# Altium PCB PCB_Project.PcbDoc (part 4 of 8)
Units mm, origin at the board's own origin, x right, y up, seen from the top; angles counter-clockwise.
Board outline 250 x 200 mm, 6 copper layers (Top Shielding/Sig, Sig 1, PWR, GND, Sig 4, Bottom Shielding/Sig), stack 1.568 mm thick; 736 components, 420 nets, 1929 pads, 2185 vias.
Unrouted connection lines stored in the file: 47.
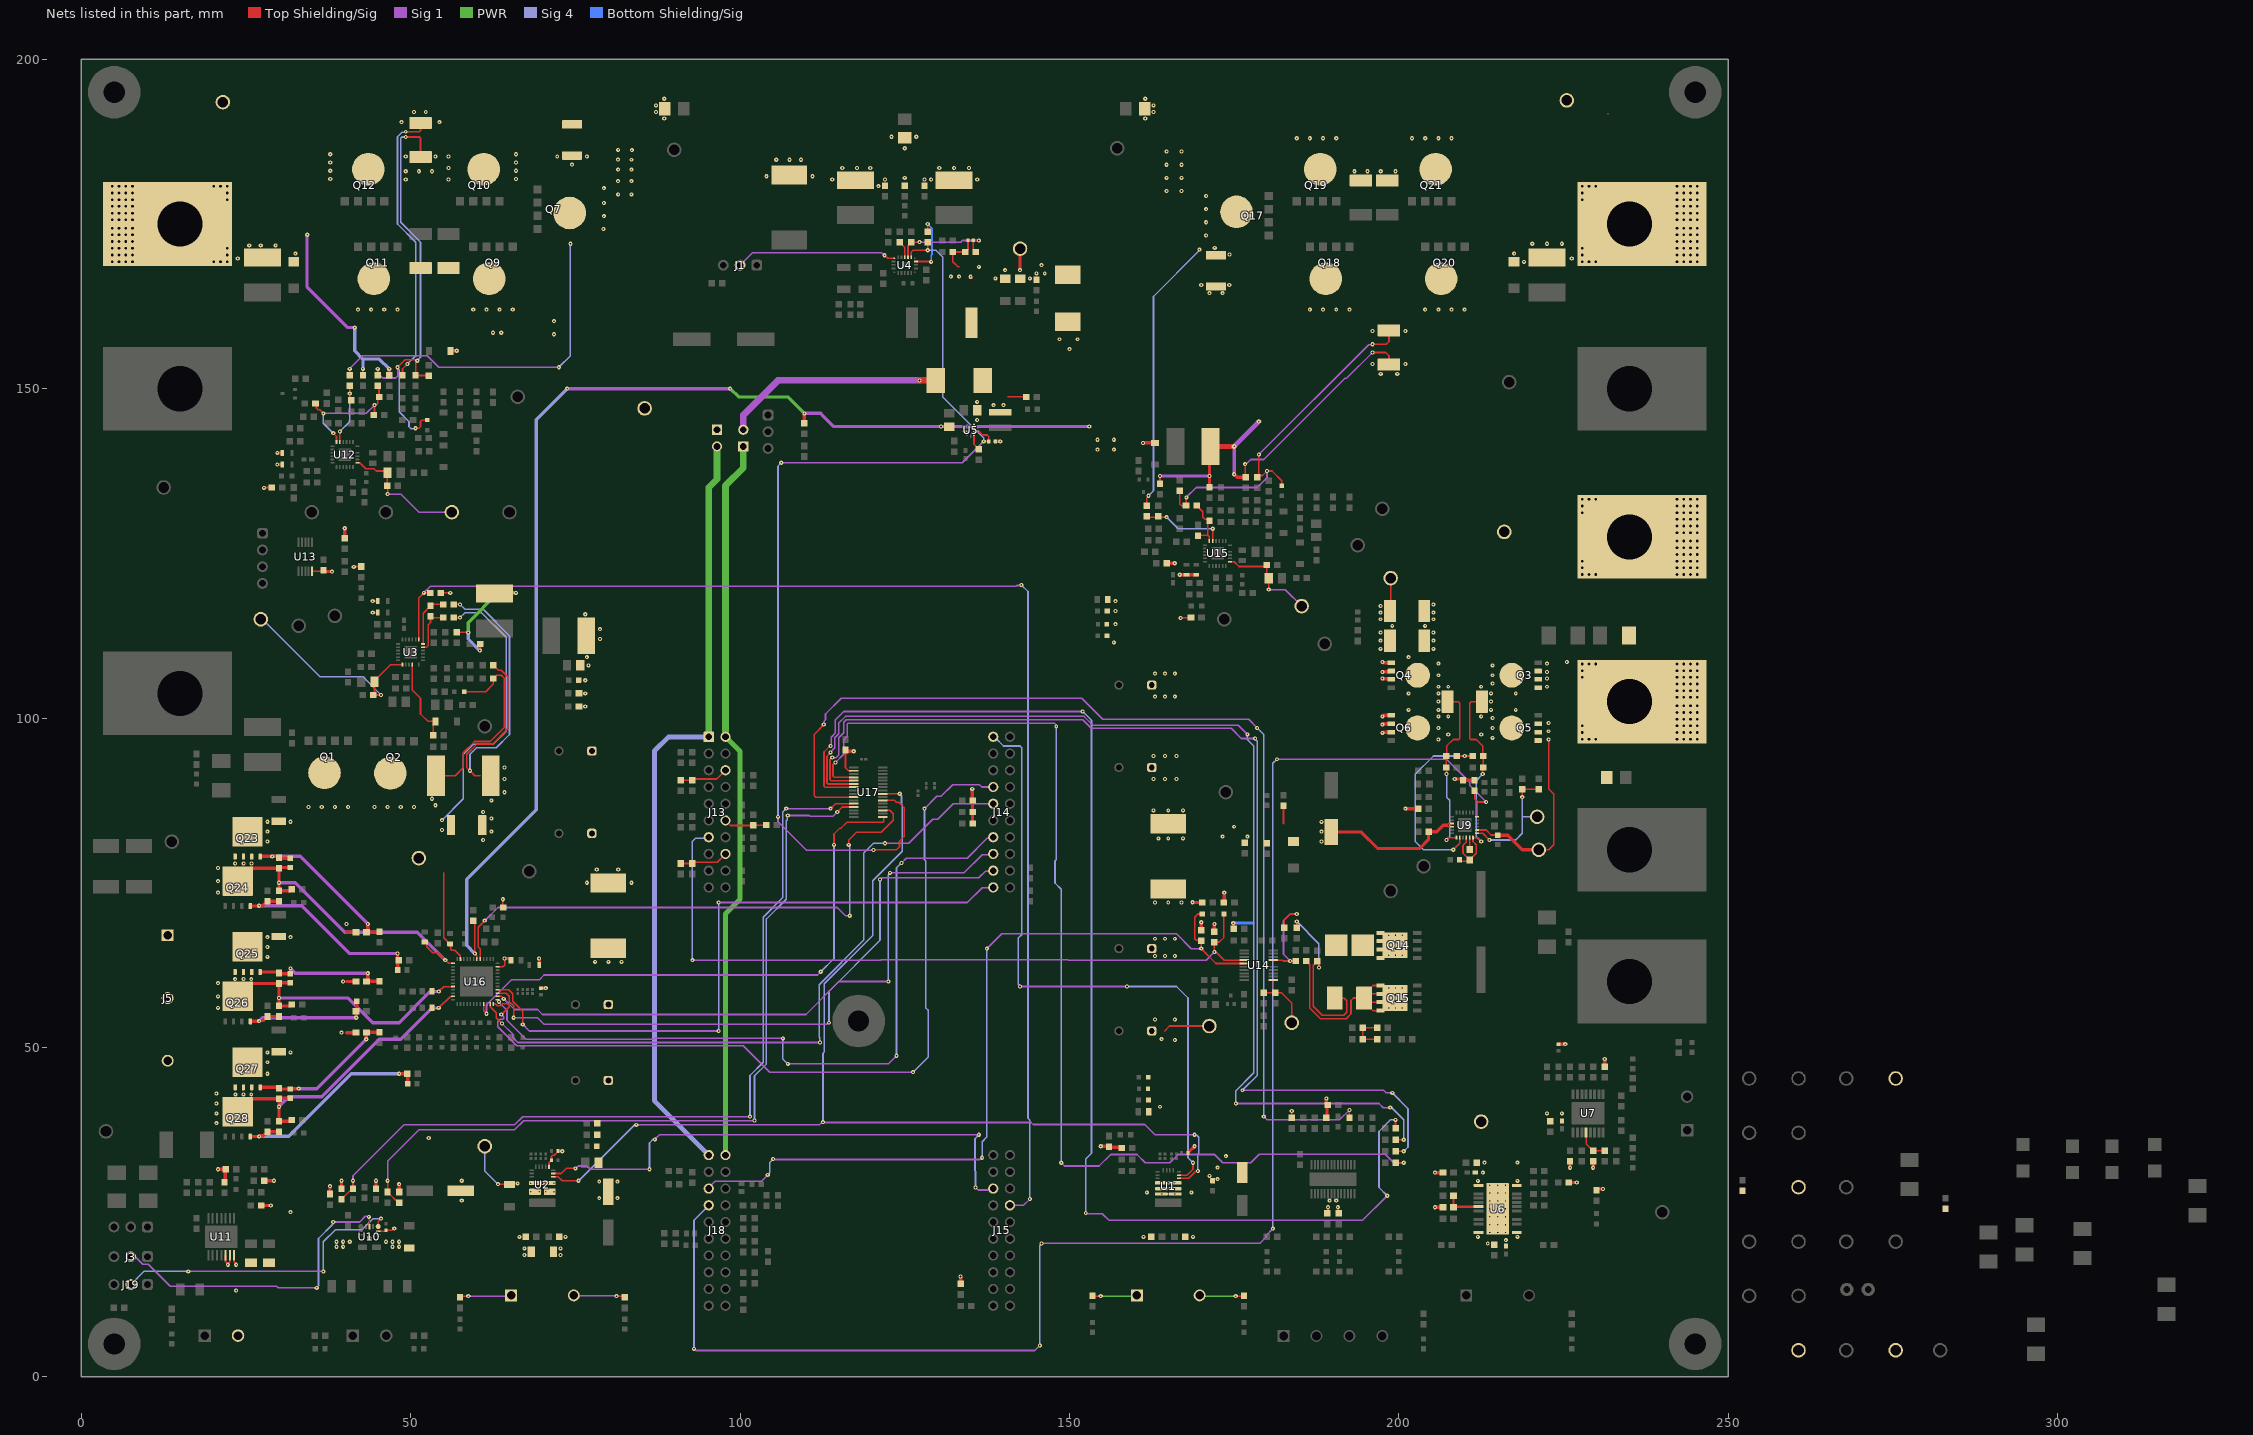
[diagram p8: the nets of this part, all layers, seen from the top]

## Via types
v1: diameter 0.635, hole 0.254, Top Shielding/Sig to Bottom Shielding/Sig, tented both sides, 778 vias
v2: diameter 0.6, hole 0.254, Top Shielding/Sig to Bottom Shielding/Sig, tented both sides, 726 vias
v3: diameter 0.813, hole 0.406, Top Shielding/Sig to Bottom Shielding/Sig, 522 vias
v4: diameter 0.5, hole 0.2, Top Shielding/Sig to Bottom Shielding/Sig, tented both sides, 95 vias
v5: diameter 0.5, hole 0.2, Top Shielding/Sig to Bottom Shielding/Sig, 39 vias
v6: diameter 0.635, hole 0.254, Top Shielding/Sig to Bottom Shielding/Sig, 10 vias
v7: diameter 0.63, hole 0.33, Top Shielding/Sig to Bottom Shielding/Sig, tented both sides, 6 vias
v8: diameter 0.75, hole 0.254, Top Shielding/Sig to Bottom Shielding/Sig, tented both sides, 6 vias
v9: diameter 0.5, hole 0.2, Top Shielding/Sig to Bottom Shielding/Sig, tented top, 3 vias

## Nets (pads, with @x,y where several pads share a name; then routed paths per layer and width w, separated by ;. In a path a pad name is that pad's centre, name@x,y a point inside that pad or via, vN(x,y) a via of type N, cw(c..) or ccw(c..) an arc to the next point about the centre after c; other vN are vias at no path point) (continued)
3V3: C23.1 C105.1 C128.1 C189.2 C199.1 D53.2 D54.2 J16.1 R3.2 R4.2 R6.1 R18.1 R35.2 R39.2 R40.2 R41.2 R61.2 R63.1 R64.2 R66.2 R71.2 R76.1 R79.2 R82.2 R88.1 R97.2 R98.2 R104.2 R123.2 R124.2 R125.2 R129.2 R130.2 R134.2 R136.2 R138.2 R142.2 R146.2 R149.2 R156.2 R183.2 R184.2 R186.2 R208.1 R210.1 R214.2 R215.2 R244.2 R245.2 R247.2 R257.1 R262.2 R267.2 R290.1 R291.1 R292.1 R297.2 R302.2 TP41.1 U2.11 U10.5 U13.10 U16.23 U17.2 | length 81.7
  Top Shielding/Sig w0.2: U16.23@63.212,62.25 64,62.25 64.25,62.5 v1(64.25,63.5) ; C189.2@64.995,63.5 C189.2@65.245,63.25
  Top Shielding/Sig w0.25: v2@27.75,135 R183.2@28.9,135 ; U13.10@35,122.5 35,122.325 35.025,122.3 C128.1@36.6,122.3 ; v1@41.5,123 R39.2@42.5,123 ; v1(44.25,116) R40.2@45,116 ; v1(44.25,117.75) R41.2@45,117.75 ; U10.5@45.1,22.075 46.075,22.075 C105.1@46.25,22.25 47.161,22.25 47.411,22.5 v1(47.5,22.5) ; R35.2@54.55,119 v1(56,119) ; v1(64,72.5) 64,71.3 R267.2@64.05,71.25 ; U2.11@71,31.875 71,32.5 C23.1@71.25,32.75 ; C23.1@71.375,32.875 71.375,33.479 71.521,33.625 71.8,33.625 72.375,34.2 R18.1@72.375,34.25 v1(73,34.25) ; C199.1@116,95.15 116,92.444 116.419,92.025 116.975,92.025 U17.2@117,92 ; v2@167,115.25 R244.2@168.45,115.25 ; R215.2@173.45,72 R215.2@173.5,72.05 ; R98.2@183.75,39.3 v1(183.75,40.344)
  Top Shielding/Sig w0.5: v1(20.75,31.5) R136.2@21.95,31.5 21.85,31.4 21.85,29.65 R146.2@21.75,29.55 ; R142.2@27.3,26 v1(28.75,26) ; R149.2@27.8,29.75 v1(29.25,29.75) ; v2(29.75,138.5) R184.2@30.5,138.5 ; v2(29.75,140.25) R186.2@30.5,140.25 ; C128.1@36.95,122.25 v1@38.026,122.25 ; R134.2@37.75,27.75 v1(37.75,28.95) ; R129.2@39.5,28.55 v1(39.5,29.75) ; R302.2@40,127.3 v1(40,128.8) ; R138.2@44.75,28.55 v1(44.75,29.75) ; R130.2@48.25,28.05 v1(48.25,29.25) ; D53.2@56.025,155.75 v6(57,155.75) ; v1(64.25,63.5) C189.2@64.995,63.5 ; R262.2@69.5,62.5 v1(69.5,63.5) ; R257.1@69.75,59 v1(70.5,59) ; C199.1@116,95.15 116.2,94.95 v1(117.25,94.95) ; R156.2@133.5,14.1 v1@133.5,15.1 ; v1(135.25,89.25) 135.25,87.55 R290.1@135.3,87.5 R292.1@135.3,85.75 R291.1@135.3,84 ; R61.2@138.75,142 v1(139.5,142) ; v1(154.75,35) 155.95,35 R3.2@156,34.95 156.1,34.85 157.85,34.85 R4.2@157.95,34.75 ; v2@161.275,141.775 D54.2@163,141.775 ; R297.2@164.8,123.5 v1@165.75,123.5 ; v1(166.75,121.75) 167.55,121.75 R247.2@167.75,121.75 ; R247.2@167.921,121.75 168.096,121.75 169.05,121.75 R245.2@169.421,121.75 ; R6.1@168,34 168,34.05 168.05,34.05 v1(169,35) ; v1@169,72 R214.2@170.15,72 ; R208.1@170,67.8 v1(170,69) ; R210.1@172,67.55 v1(172,68.75) ; R215.2@173.5,72.05 v1@173.5,73.25 ; R97.2@189,39.3 189.1,39.4 189.1,41.15 R104.2@189.2,41.25 189,41.45 v1(189,42.25) ; v1(201,86.25) R125.2@202.95,86.25 ; v1(205.5,25.75) R71.2@206.7,25.75 ; v1(205.5,31) R63.1@206.7,31 ; v1(208.5,90.75) 209.55,90.75 R124.2@209.75,90.55 R123.2@211.5,90.55 ; R88.1@224.25,50.5 v1(225.25,50.5) ; R66.2@225.8,29.5 v1(227,29.5) ; v1(226,31.75) R76.1@226,32.7 ; v1(229.5,31.75) R79.2@229.5,32.7 ; R64.2@230,28.3 230.2,28.5 v1(231,28.5) ; R82.2@231.25,47.05 v1(231.25,48.25)
  other v1: 133.459,15.219 168.701,72.028 173.5,73.5 38.056,122.231 41.348,122.954 166,123.5
  other v2: 166.893,115.196 27.727,134.945 161.154,141.744
3V3_MCU_12: J13.1 J16.2 J18.41 | length 118.3
  PWR w1: J13.1@95.25,97.155 95.25,135 96.5,136.25 J16.2@96.5,141.23
  Sig 4 w0.75: J13.1@95.054,97.155 89.155,97.155 87,95 87,41.905 J18.41@95.25,33.655
5V_AM26: D12.1 J17.2 | length 33.5
  Top Shielding/Sig w1: v2(127.25,151.25) D12.1@129.681,151.25
  Sig 1 w1: J17.2@100.5,143.868 100.5,146 105.75,151.25 v2(127.25,151.25)
5V_BUCK: C69.1 D12.2 L5.2 R58.2 U5.3 | length 2.8
  Top Shielding/Sig w0.25: 140.625,148.75 R58.2@143.45,148.75
  other v2: 136,145.25 138.5,147.5 140,147.5 136,148
5V_MCU_12: J13.21 J17.1 J18.61 | length 110.8
  PWR w0.75: J18.61@97.79,33.655 97.79,70.29 100,72.5 100,94.945 J13.21@97.79,97.155
  PWR w1: J13.21@97.79,97.155 97.79,135.29 100.5,138 J17.1@100.5,141.452
12V: C7.2 C8.2 C9.2 C10.2 C11.1 C12.1 C70.1 C73.1 C74.1 C75.1 C76.1 C82.1 C83.1 C87.1 C88.1 C95.1 C96.1 C138.2 C167.1 D10.1 D39.2 L1.1 Q4.1 Q4.2 Q4.3 Q6.1 Q6.2 Q6.3 R57.2 R109.2 R110.2 R116.2 R192.1 R195.1 R196.2 R198.1 R200.2 R213.1 R306.1 R307.1 TP10.1 TP20.1 TP43.1 TP45.1 U5.6 U6.1 U6.9 U6.10 U6.18 U6.19 U9.15 U9.16 U16.30 | length 251.3
  Top Shielding/Sig w0.212: v1(59.75,64.25) 59.75,64.241 60.06,63.93 U16.30@60.062,63.4 U16.30@60.062,63.4 ; R213.1@184.5,68.175 v1(184.5,69.125) ; v1(187.875,62.125) 187.875,62.825 R196.2@187.625,63.075 187.625,63.05 187.256,62.681 187.231,62.681 187,62.45 187,56.25 188.375,54.875 191.625,54.875 192.125,55.375 192.125,57.125 191.75,57.5 R195.1@190.29,57.5
  Top Shielding/Sig w0.25: C167.1@59.5,69.2 59.75,68.95 v1(59.75,64.25) ; 182.5,84 R116.2@182.5,86.7 ; R110.2@198.65,116.25 198.75,116.35 TP10.1@198.75,121.25 ; U9.16@208.1,83.5 207.5,83.5 207.25,83.75 207.5,84 U9.15@208.1,84
  Top Shielding/Sig w0.5: R57.2@109.75,144.75 v2(109.75,146.25) ; v1(174.875,68.875) 174.901,68.849 174.901,68.049 R200.2@174.95,68 ; C95.1@189.75,82.7 194.3,82.7 196.8,80.2 203.2,80.2 204.5,81.5 204.5,82.7 C96.1@204.55,82.75 205.75,82.75 206.75,83.75 207.25,83.75 ; v2(197.5,97.75) 197.527,97.75 197.642,97.865 Q6.3@198.863,97.865 ; v2(197.5,99) 197.527,99 197.662,99.135 Q6.2@198.863,99.135 ; v2(197.5,100.25) 197.527,100.25 197.682,100.405 Q6.1@198.863,100.405 ; v2(197.5,106) 197.527,106 197.562,105.965 198.763,105.965 Q4.3@198.863,105.865 ; v2(197.5,107) 197.527,107 197.562,107.035 198.763,107.035 Q4.2@198.863,107.135 ; v2(197.5,108.5) 197.527,108.5 197.622,108.405 Q4.1@198.863,108.405
  Sig 1 w0.5: v2(73.75,150) v2(98.5,150) v2@98.52,150 ; v2@110,146.25 112.25,146.25 112.5,146 114.25,144.25 v1@130.375,144.25 ; v1(130.5,144.25) v1(153,144.25)
  PWR w0.5: v2@98.52,150 99.77,148.75 107.25,148.75 v2(109.75,146.25)
  Sig 4 w0.212: v1(184.5,69.125) 187.875,65.75 v1(187.875,62.125)
  Sig 4 w0.5: v1(59.75,64.25) 58.5,65.5 58.5,75.5 69.052,86.052 69.052,145.302 v2(73.75,150)
  Bottom Shielding/Sig w0.5: v1(174.875,68.875) 177.875,68.875
  other v1: 189.25,25.75 190.75,25.75 189.5,26.75 190.5,26.75 154.25,140.75 156.75,140.75 154.25,142.25 156.75,142.25
  other v2: 213.5,20.25 216.25,20.75 212,21.25 218,21.25 212,29.75 218,29.75 212.75,31 213,32.5 218,32.5 222.5,40 224.75,40 188.25,81.25 163.5,81.75 165,81.75 167.25,81.75 173.25,82 177,82 188.25,82.75 175,83.5 188.25,84.25 162.75,86 165,86 167.25,86 162.75,90.75 164.5,90.75 166.25,90.75 162.75,94.25 164.5,94.25 166.25,94.25 163,103.25 164.5,103.25 166,103.25 163,106.75 164.5,106.75 166,106.75 197.25,110.5 156.75,111.5 197.25,111.75 197.25,113 199,114 157,114.25 197.25,115 197.25,116 157,116.25 197.25,117 157,117.75 150,156 148.5,157.5 151.25,157.5
  other v4: 213.8,21.9 215,21.9 216.2,21.9 213.8,23.1 215,23.1 216.2,23.1 213.8,24.3 215,24.3 216.2,24.3 213.8,25.5 215,25.5 216.2,25.5 213.8,26.7 215,26.7 216.2,26.7 213.8,27.9 215,27.9 216.2,27.9 213.8,29.1 215,29.1 216.2,29.1
12V_DRV8245: C1.2 C2.2 C13.1 C14.1 C15.2 C16.2 C17.2 C18.2 L1.2 TP1.1 U1.4 | length 8
  Top Shielding/Sig w0.25: 164.45,52.5 165.2,53.25 TP1.1@171.25,53.25
  Top Shielding/Sig w0.75: C1.2@176.25,31 176.25,30.675 C1.2@176.675,30.25
  other v2: 172.5,30 171.25,30.5 172.5,31.75 173.75,33.5 163.75,41 166,51.125 164,51.25 163,54.25 166,54.25 163,63.875 164.5,63.875 166,63.875 163,66.5 164.5,66.5 166,66.5 163,72 165,72 167,72
  other v5: 164,29.45 165,29.45 166,29.45
12V_IN: C94.2 D24.1 D25.1 Q3.1 Q3.2 Q3.3 Q5.1 Q5.2 Q5.3 T2.1 TP9.1 U9.2 | length 39
  Top Shielding/Sig w0.25: U9.2@211.9,83 213.25,83 214,82.25 214.95,82.25 C94.2@215,82.2 ; TP9.1@221.25,80 222.75,80 223.5,80.75 223.5,88.474 222.75,89.224 v2(222.75,96.75)
  Top Shielding/Sig w0.5: C94.2@215,82.2 216.55,82.2 218.75,80 TP9.1@221.25,80
  Top Shielding/Sig w0.75: T2.1@227.808,108.167 233.475,102.5 T2.1@235,102.5
  other v2: 222.75,98 222.75,99.25 222.5,104.75 222.5,106 222.5,107 222.5,108.25 225.5,108.5
  other v3: 227.856,96.785 228.872,96.785 229.888,96.785 242.239,96.785 243.255,96.785 244.271,96.785 245.287,96.785 227.856,97.801 242.239,97.801 243.255,97.801 244.271,97.801 245.287,97.801 227.856,98.817 242.239,98.817 243.255,98.817 244.271,98.817 245.287,98.817 242.239,99.833 243.255,99.833 244.271,99.833 245.287,99.833 242.239,100.849 243.255,100.849 244.271,100.849 245.287,100.849 242.239,101.865 243.255,101.865 244.271,101.865 245.287,101.865 242.239,103.135 243.255,103.135 244.271,103.135 245.287,103.135 242.239,104.151 243.255,104.151 244.271,104.151 245.287,104.151 242.239,105.167 243.255,105.167 244.271,105.167 245.287,105.167 227.856,106.183 242.239,106.183 243.255,106.183 244.271,106.183 245.287,106.183 227.856,107.199 242.239,107.199 243.255,107.199 244.271,107.199 245.287,107.199 227.856,108.215 228.872,108.215 229.888,108.215 242.239,108.215 243.255,108.215 244.271,108.215 245.287,108.215
48V: C28.1 C29.1 C32.2 C33.2 C34.2 C35.1 C41.1 C42.1 C43.1 C106.1 C107.1 C109.1 C110.1 C115.1 C118.1 C145.1 C146.1 C165.1 C168.1 C172.1 C174.1 C175.1 C180.1 C182.1 D32.2 J7.2 L2.1 L4.1 Q9.5-6-7-8 Q11.5-6-7-8 Q23.5 Q23.6 Q23.7 Q23.8 Q23.9@25.25,82.755 Q25.5 Q25.6 Q25.7 Q25.8 Q25.9@25.25,65.255 Q27.5 Q27.6 Q27.7 Q27.8 Q27.9@25.25,47.755 R21.1 R22.2 R26.1 R27.2 R28.2 R36.2 R159.2 R160.2 R161.2 R216.1 R217.2 R223.1 R224.2 R238.2 T3.1 TP2.1 TP14.1 TP24.1 TP39.1 U10.3 U11.12 U11.13 U11.14 U16.35 | length 161
  Top Shielding/Sig w0.2: C172.1@56,65.725 56.083,65.642 56.083,64.892 56.2,64.775 56.725,64.775 57.562,63.938 U16.35@57.562,63.4
  Top Shielding/Sig w0.25: U11.12@21.9,18.45 21.9,17.454 v1@22.25,17.104 ; v1(22.25,17) v1@22.25,17.104 ; U11.13@22.55,18.45 22.55,17.404 v1@22.25,17.104 ; U11.14@23.2,18.45 23.2,17.404 23.5,17.104 v1(23.5,17) ; 55,76.5 55,66.65 55.925,65.725 C172.1@56,65.725 ; R22.2@56.55,117.25 v1(57.5,117.25) ; R27.2@57,113.05 57.05,113 v1(58.75,113) ; 60.568,91.25 59.75,91.25 v1(59,92) 58.5,92.5 58.5,94.5 60,96 62.375,96 64.75,98.375 64.75,106.25 63.75,107.25 63.325,107.25 62.575,108 R28.2@62.55,108 ; R217.2@163.75,135.55 v1(163.75,136.75) ; v2(176.678,138.54) 176.678,136.822 R224.2@176.75,136.75 ; v1(196,155.5) 198,155.5 198.5,155 R223.1@198.5,153.65
  Top Shielding/Sig w0.5: 40.25,52.25 C182.1@41.7,52.25 ; 40.25,60 C175.1@41.7,60 ; 40.25,67.5 C165.1@41.7,67.5 ; v1(60.5,110.25) 60.525,110.275 60.525,111.225 R36.2@60.55,111.25 ; R238.2@171.25,135.05 v1(171.25,136.75) 171.25,141.1 C42.1@171.4,141.25 ; v1(175,137) 175.037,137 175.487,136.55 R224.2@176.75,136.55
  Top Shielding/Sig w0.75: C42.1@171.4,141.25 v8(175,141.25)
  Sig 1 w0.25: v2@176.75,138.5 177.5,139.25 179.5,139.25 191.82,151.57 192.07,151.57 v1(196,155.5)
  Sig 1 w0.5: v1(163.75,136.75) v1(171.25,136.75) ; v1(175,137) v8(175,141.25)
  Sig 1 w0.75: v8(175,141.25) v1(178.75,145)
  PWR w0.5: v1(58.75,113) 58.75,114.5 63.25,119 v1(66,119)
  Sig 4 w0.25: v1(57.5,117.25) 58.25,116.5 61,116.5 65,112.5 65,97.5 63,95.5 60,95.5 59,94.5 v1(59,92)
  Sig 4 w0.5: v1(58.75,113) 58.75,112 v1(60.5,110.25)
  other v1: 23.5,13.107 38.75,19.75 39.75,19.75 47.25,19.75 48.25,19.75 38.75,20.5 39.75,20.5 40.75,20.5 46.25,20.5 47.25,20.5 48.25,20.5 31.75,25 57.75,26.75 57.75,29.75 52.75,36.25 28.25,46 28.25,49.25 31.75,49.25 39.5,52.25 39.75,60 28.25,63.75 28.25,66.75 31.75,66.75 40.25,68.75 76.75,75 83.5,75 78.25,77 81.5,77 28.25,81.25 28.25,84.25 31.75,84.25 64.25,88.75 64.25,90.75 64.25,92.5 76.5,101.75 76.5,103.75 76.5,105.75 77,108 76.75,109.25 78.75,112 78.75,113.5 76.5,115.75 197.25,152.25 199.75,152.25 196,153.75 201,153.75 71.75,158.25 62.5,158.5 63.75,158.5 71.75,160.25 42,162 44,162 46,162 48,162 59.5,162 61.5,162 63.5,162 65.5,162 171.25,164.5 173.25,164.5 170,165.75 174.25,165.75 121,180.75 114,181.75 122,181.75 128,181.75 129,181.75 136,181.75 125,182 104,182.25 111,182.25 115.5,183.5 117.75,183.5 119.75,183.5 130.25,183.5 132.5,183.5 134.75,183.5 105.5,184.75 107.5,184.75 109.25,184.75 125,186.5 123,188.25 126.75,188.25
  other v2: 28.25,47.75 28.25,65.25 61,81.5 28.25,82.75 62.25,82.75 62.25,84.75 61,85.75 62.25,87.5
  other v3: 227.856,121.785 228.872,121.785 229.888,121.785 242.239,121.785 243.255,121.785 244.271,121.785 245.287,121.785 227.856,122.801 242.239,122.801 243.255,122.801 244.271,122.801 245.287,122.801 227.856,123.817 242.239,123.817 243.255,123.817 244.271,123.817 245.287,123.817 242.239,124.833 243.255,124.833 244.271,124.833 245.287,124.833 242.239,125.849 243.255,125.849 244.271,125.849 245.287,125.849 242.239,126.865 243.255,126.865 244.271,126.865 245.287,126.865 242.239,128.135 243.255,128.135 244.271,128.135 245.287,128.135 242.239,129.151 243.255,129.151 244.271,129.151 245.287,129.151 242.239,130.167 243.255,130.167 244.271,130.167 245.287,130.167 227.856,131.183 242.239,131.183 243.255,131.183 244.271,131.183 245.287,131.183 227.856,132.199 242.239,132.199 243.255,132.199 244.271,132.199 245.287,132.199 227.856,133.215 228.872,133.215 229.888,133.215 242.239,133.215 243.255,133.215 244.271,133.215 245.287,133.215
48V_BAT1: C117.1 D33.2 D34.2 R153.1 R154.2 R162.1 R164.2 R177.2 T4.1 TP15.1 | length 74
  Top Shielding/Sig w0.25: R154.2@42.75,152.05 v1(42.75,153) ; R164.2@48.75,152 48.75,153 v1(49.5,153.75) ; v2(49.25,189) 51.354,189 51.5,189.146 R162.1@51.5,190.35
  Top Shielding/Sig w0.5: R177.2@46.75,152.05 v1@46.75,152.875
  Sig 1 w0.5: v1@34.25,173.25 34.25,165.5 40.474,159.276 41.474,159.276 v6(41.5,159.25)
  Sig 4 w0.25: v2(49.25,189) 49.183,188.933 48.683,188.933 48,188.25 48,175 50.75,172.25 50.75,155 v1(49.5,153.75)
  Sig 4 w0.5: v6(41.5,159.25) 41.5,155.75 42.75,154.5 ; v1(42.75,153) 42.75,154.5 ; v1(46.75,153) 45.25,154.5 42.75,154.5
  other v1: 23.75,169.75 32.5,170.5 25.5,171.75 27.25,171.75 29.5,171.75 34.311,173.362 88.5,191 87.25,192 87.25,193 88.5,194
  other v2: 48.599,190.453 54.349,190.453 50.5,192 52.289,191.995
  other v3: 4.713,169.285 5.729,169.285 6.745,169.285 7.761,169.285 20.112,169.285 21.128,169.285 22.144,169.285 4.713,170.301 5.729,170.301 6.745,170.301 7.761,170.301 22.144,170.301 4.713,171.317 5.729,171.317 6.745,171.317 7.761,171.317 22.144,171.317 4.713,172.333 5.729,172.333 6.745,172.333 7.761,172.333 4.713,173.349 5.729,173.349 6.745,173.349 7.761,173.349 4.713,174.365 5.729,174.365 6.745,174.365 7.761,174.365 4.713,175.635 5.729,175.635 6.745,175.635 7.761,175.635 4.713,176.651 5.729,176.651 6.745,176.651 7.761,176.651 4.713,177.667 5.729,177.667 6.745,177.667 7.761,177.667 4.713,178.683 5.729,178.683 6.745,178.683 7.761,178.683 22.144,178.683 4.713,179.699 5.729,179.699 6.745,179.699 7.761,179.699 22.144,179.699 4.713,180.715 5.729,180.715 6.745,180.715 7.761,180.715 20.112,180.715 21.128,180.715 22.144,180.715
48V_BAT2: C148.1 D43.2 D44.2 Q19.5-6-7-8 Q21.5-6-7-8 R220.2 R222.2 T6.1 TP25.1 | length 0
  other v1: 219,169.25 226.25,169.75 217.5,170.5 220.25,172 222.5,172 224.75,172 193.25,183 195.25,183 197.25,183 199.5,183 184.5,188 186.5,188 188.5,188 190.5,188 202,188 204,188 206,188 208,188 161.5,191 162.75,192 162.75,193 161.5,194
  other v3: 227.856,169.285 228.872,169.285 229.888,169.285 242.239,169.285 243.255,169.285 244.271,169.285 245.287,169.285 227.856,170.301 242.239,170.301 243.255,170.301 244.271,170.301 245.287,170.301 227.856,171.317 242.239,171.317 243.255,171.317 244.271,171.317 245.287,171.317 242.239,172.333 243.255,172.333 244.271,172.333 245.287,172.333 242.239,173.349 243.255,173.349 244.271,173.349 245.287,173.349 242.239,174.365 243.255,174.365 244.271,174.365 245.287,174.365 242.239,175.635 243.255,175.635 244.271,175.635 245.287,175.635 242.239,176.651 243.255,176.651 244.271,176.651 245.287,176.651 242.239,177.667 243.255,177.667 244.271,177.667 245.287,177.667 227.856,178.683 242.239,178.683 243.255,178.683 244.271,178.683 245.287,178.683 227.856,179.699 242.239,179.699 243.255,179.699 244.271,179.699 245.287,179.699 227.856,180.715 228.872,180.715 229.888,180.715 242.239,180.715 243.255,180.715 244.271,180.715 245.287,180.715
48V_DRV8263: C19.1 C20.1 C27.2 C30.1 C31.1 C36.1 C37.2 C38.2 L2.2 TP3.1 U2.4 | length 8.3
  Top Shielding/Sig w0.25: v1(63.25,29.25) 64.95,29.25 C20.1@65,29.2
  Sig 4 w0.25: TP3.1@61.25,35 61.25,31.25 v1(63.25,29.25)
  other v2: 78.625,27.125 81.375,27.125 66.25,29.375 78.625,29.625 81.375,29.625 78,63 80,63 82,63
  other v4: 68.25,29.4 69.125,29.4 70,29.4 70.875,29.4 71.75,29.4
48V_Q22-24_3: Q18.5-6-7-8 Q20.5-6-7-8 R223.2 R225.2 R226.2 R301.1 RNTC_3.2 | length 56.1
  Top Shielding/Sig w0.25: R301.1@166.75,134.5 166.75,132.5 167,132.25 R226.2@167.5,132.25 ; R226.2@167.7,132.25 167.75,132.3 v1(167.75,133.5) ; R225.2@178.5,136.55 178.768,136.818 179.318,136.818 v1(180,137.5) 180.75,137.5 182.25,136 RNTC_3.2@182.25,135.275 ; R225.2@178.5,136.75 178.575,136.75 178.75,136.925 v2(178.75,140) ; v1(196,156.75) 198.104,156.75 198.5,157.146 R223.2@198.5,158.85
  Sig 1 w0.25: v1(167.75,133.5) 169.25,135 178.5,135 180,136.5 v1(180,137.5) ; v2(178.75,140) 195.426,156.676 195.926,156.676 v1(196,156.75)
  other v1: 196,158.75 201,158.75
  other v2: 186.5,162 188.5,162 190.5,162 192.5,162 204,162 206,162 208,162 210,162
482H85_DIAG_EN_5: J3.2 U10.8 | length 47.8
  Top Shielding/Sig w0.25: v1(43.658,24.282) 43.725,24.215 43.725,22.825 U10.8@43.75,22.8
  Sig 1 w0.25: J3.2@8.262,18.16 9.322,17.1 10.15,17.1 13.5,13.75 29.634,13.75 29.884,13.5 v1(35.75,13.5) ; v1(38.25,23.5) 42.25,23.5 43.106,24.356 43.584,24.356 v1(43.658,24.282)
  Sig 4 w0.25: v1(35.75,13.5) 35.75,13.589 36,13.839 36,21 38.176,23.176 38.176,23.426 v1(38.25,23.5)
482H85_SEL_5: J19.2 U10.6 | length 46.1
  Top Shielding/Sig w0.25: U10.6@45.075,22.825 45.082,22.832 45.082,23.582 v2(45.5,24)
  Sig 1 w0.25: v1(16.25,16.005) 36.745,16.005 v2(36.75,16)
  Sig 4 w0.25: J19.2@7.5,14 9.5,16 16.245,16 v1(16.25,16.005) ; v2(36.75,16) 36.75,20.5 38.592,22.342 42.625,22.342 44.284,24 v2(45.5,24)
_1: J15.80 R7.1 R17.1 R67.1 R86.1 R258.1 R294.1 | length 317.9
  Top Shielding/Sig w0.25: v1(67,56.75) R258.1@67,58.17 ; R17.1@69,33.83 v1(69,35.25) ; R294.1@129.5,89.42 130.08,89.42 v1(130.5,89) ; v1(163.75,37.5) 163.75,35.25 164.5,34.5 R7.1@164.5,33.83 ; R67.1@222.05,26 v1(225,26) ; R86.1@227.75,47.05 v1(227.75,48.25)
  Sig 1 w0.25: v1(67,56.75) 71.75,56.75 73.75,58.75 83.75,58.75 86.25,56.25 v2(108.75,56.25) ; v2(108.75,49) 108.821,49 109.071,48.75 121.25,48.75 128.75,56.25 v1(149.965,56.25) ; v1(139.25,39.25) 139.75,39.75 147.75,39.75 148.358,39.142 150.933,39.142 151.325,38.75 161.636,38.75 162.886,37.5 v1(163.75,37.5) ; v1(149.965,50.75) 150.054,50.75 150.304,50.5 223.5,50.5 224.75,49.25 226.75,49.25 v1(227.75,48.25)
  Sig 4 w0.25: v1(67,56.75) 69,54.75 v1(69,35.25) ; v2(108.75,49) v2(108.75,56.25) ; v1(128.857,56.25) 128.893,56.285 128.893,83.393 129.396,83.896 129.5,83.896 129.5,84.949 129.535,84.984 129.535,86.921 130.5,87.886 v1(130.5,89) ; J15.80@138.5,33.75 138.5,33.859 139.25,34.609 v1(139.25,39.25) ; v1(149.5,39.142) 149.5,39.247 149.3,39.447 149.3,50.085 v1(149.965,50.75) ; v1(149.965,56.25) 149.965,50.785 v1@149.982,50.768 ; v1(225,26) 227.5,26 228.25,26.75 228.25,31 227.5,31.75 227.5,36 225.75,37.75 225.75,44.75 227.75,46.75 v1(227.75,48.25)
  other v1: 129.5,84
BUCK_PG_1: R50.1 R61.1 U4.2 U5.1 U17.22 | length 158.2
  Top Shielding/Sig w0.25: v1(120.264,79.958) 120.306,80 123.75,80 124.2,80.45 124.2,81.314 124.9,82.014 124.9,86.417 124.095,87.222 123.733,87.222 123.455,87.5 U17.22@122.25,87.5 ; U4.2@126,169.95 126,170.75 126.25,171 v1(128.5,171) R50.1@128.5,172.2 ; U5.1@135.762,143.5 136.325,143.5 136.85,142.975 137.525,142.975 137.75,142.75 R61.1@137.75,142 v1(137,142)
  Sig 1 w0.25: v1(105.75,85) 105.75,84.25 110.042,79.958 v1(120.264,79.958) ; v1(106.25,138.75) 133.75,138.75 v1(137,142)
  Sig 4 w0.25: v1(105.75,85) 105.75,138.25 v1(106.25,138.75) ; v1(128.5,171) 129.75,171 130.75,170 130.75,148.75 137,142.5 v1(137,142)
CAP_11: C98.1 U9.23 | length 1.8
  Top Shielding/Sig w0.25: C98.1@210.75,80.05 U9.23@210.75,81.85
Cobra_en_pin_14: J1.2 U4.7 | length 24.5
  Top Shielding/Sig w0.25: v1@122,170.25 122.431,169.819 U4.7@123.431,169.819
  Sig 1 w0.25: J1.2@100,168.75 101.893,170.643 121.46,170.643 121.84,170.263 v1(121.944,170.263)
Cobra_VCC_14: C66.1 U4.4 | length 2.6
  Top Shielding/Sig w0.25: C66.1@124.25,172.2 124.25,172.175 125,171.425 U4.4@125,169.95
Cobra_Vout_14: C62.2 C63.2 C68.2 D10.2 L3.2 R47.2 R50.2 R52.2 R53.2 TP8.1 U4.20 | length 19.7
  Top Shielding/Sig w0.25: U4.20@126.7,169.3 v2@128.95,169.3 ; R50.2@128.5,173.8 v1(128.5,175) ; 133.25,168.5 133.075,168.5 132.3,169.275 R52.2@132.3,170.75 R53.2@134.2,170.75 134.225,170.75 134.6,171.125 C68.2@134.6,172.5 ; v1(135,167) 135.25,166.75
  Top Shielding/Sig w0.5: v2(142.5,168) TP8.1@142.5,171.25
  Bottom Shielding/Sig w0.25: v1(128.5,175) 129.143,174.357 129.143,170.377 129,170.234 v2(129,169.25)
  other v2: 138.75,166.75 144,166.75 132,167 133.25,167 145,167.5 146.25,167.5 140.25,168 136.25,168.5 145.75,168.75
CS2+_TPS1214_7: C39.2 R22.1 U3.24 | length 8.3
  Top Shielding/Sig w0.25: U3.24@51.9,111.25 51.9,115.925 53,117.025 C39.2@53,117.05 53.2,117.25 R22.1@54.95,117.25
CS2-_1212_input1_2: C113.1 R155.1 U12.23 | length 10.3
  Top Shielding/Sig w0.25: U12.23@39.25,141.9 v1(39.25,143.5) ; R155.1@40.75,150.5 v1(40.75,149.25) 40.75,148.5 C113.1@41,148.25
  Sig 4 w0.25: v1(39.25,143.5) 40.75,145 v1(40.75,149.25)
CS2-_1212_input2_3: C143.1 R218.1 U15.23 | length 12.6
  Top Shielding/Sig w0.25: R218.1@161.75,130.2 R218.1@161.8,130.25 ; R218.1@161.8,130.5 163.75,130.5 v1(164.75,130.5) ; U15.23@171.75,126.9 v1(171.75,128.75)
  Sig 4 w0.25: v1(164.75,130.5) 166.5,128.75 v1(171.75,128.75)
CS2-_TPS1214_7: C39.1 R23.1 U3.23 | length 7.5
  Top Shielding/Sig w0.25: U3.23@51.9,110.75 52.409,110.75 52.659,111 52.659,114.159 53,114.5 C39.1@53,115.45 53.2,115.25 R23.1@54.95,115.25
CS+_74900_11: C93.2 R112.1 U9.20 | length 29.8
  Top Shielding/Sig w0.25: v1(208.25,80) 209.25,81 U9.20@209.25,81.85 ; C93.2@208.8,94.25 v1(210,94.25) R112.1@211.2,94.25
  Sig 4 w0.25: v1(208.25,80) 203.75,80 202.5,81.25 202.5,91.5 205.25,94.25 v1(210,94.25)
CS-_8: C139.2 R197.1 U14.17 | length 15.8
  Top Shielding/Sig w0.25: U14.17@180.95,63.25 182.375,63.25 182.5,63.125 R197.1@184.325,63.125 ; C139.2@182.625,68.175 182.625,69.375 183.5,70.25 v1(184.5,70.25)
  Sig 1 w0.25: v1(183.5,63.125) 182.5,64.125 182.5,69.25 183.5,70.25 v1(184.5,70.25)
CS-_74900_11: C93.1 C101.2 Q4.5 Q6.5 R109.1 R110.1 R111.2 U9.19 | length 26
  Top Shielding/Sig w0.25: C93.1@207.2,94.25 C101.2@207.2,92.5 207.25,92.45 v1(207.25,91.5) ; v1(207.25,81.5) 207.6,81.85 U9.19@208.75,81.85 ; C93.1@207.25,94.5 207.25,95.75 208.25,96.75 209.104,96.75 209.25,96.896 209.25,102.25 209,102.5 R111.2@207.4,102.5
  Top Shielding/Sig w0.5: C93.1@207.088,94.338 207.175,94.25 C93.1@207.2,94.25
  Sig 4 w0.25: v1(207.25,81.5) 207.75,82 207.75,87.5 207.25,88 v1(207.25,91.5)
  other v1: 207.5,97.5
  other v2: 206,96.75 206,98.5 206,100.25 207.5,100.25 201.5,101.25 206,101.25 206,102.5 201.5,103.75 206,103.75 206,104.75 207.5,104.75 206,106.5 206,108.25 201.5,109.25 205.25,110.5 205.25,111.75 205.25,113 204,114 205.25,115 205.25,116 205.25,117.25
DGATE_74900_11: R114.1 R115.1 TP12.1 U9.1 | length 19.1
  Top Shielding/Sig w0.25: U9.1@211.9,82.5 212.75,82.5 v1(213.75,81.5) ; v1(218.75,88) R115.1@218.75,89.2 R114.1@221.25,89.2
  Sig 4 w0.25: v1(213.75,81.5) 217.75,81.5 218.75,82.5 218.75,85 ; v1(218.75,88) 218.75,85 ; TP12.1@221,85 218.75,85
DI_HCS05_4: R71.1 R75.1 U6.5 | length 5.6
  Top Shielding/Sig w0.35: R75.1@208.3,27.5 R71.1@208.3,25.75 208.375,25.825 U6.5@212.1,25.825
DI_HCS10_4: R79.1 R81.1 U7.4 | length 5
  Top Shielding/Sig w0.25: U7.4@228.425,37.1 228.425,35.4 229.5,34.325 R79.1@229.5,34.3 R81.1@231.25,34.3
DIAGEN_TPS4HC120_1: R94.2 U17.10 | length 162
  Top Shielding/Sig w0.25: v1(112.713,99.031) 112.713,98.963 111.25,97.5 111.25,88.25 111.5,88 U17.10@117.25,88 ; R94.2@192.5,39.3 v1(192.5,40.5)
  Sig 1 w0.25: v1(112.713,99.031) 112.786,99.104 112.786,99.539 112.981,99.734 112.981,100.618 115.364,103 151.864,103 155.064,99.8 177.2,99.8 v2(178.5,98.5) ; v1(179.5,39.5) 180,39 191,39 v1(192.5,40.5)
  Sig 4 w0.25: v2(178.5,98.5) 179.5,97.5 v1(179.5,39.5)
DRN_2: C116.2 C124.1 R165.1 R305.2 U12.24 | length 20.6
  Top Shielding/Sig w0.25: C116.2@35.55,147.75 35.704,147.596 35.704,147.046 35.95,146.8 36.185,146.8 36.735,146.25 v1(36.75,146.25) ; v1(38.25,143.25) 38.75,142.75 U12.24@38.75,141.9 ; C124.1@44.5,146 v1(44.5,147.5) 44.574,147.574 44.801,147.574 45,147.772 45,148.55 R305.2@45.2,148.75 45.2,150.3 R165.1@45,150.5
  Sig 1 w0.25: v1(36.75,146.25) 43.25,146.25 v1(44.5,147.5)
  Sig 4 w0.25: v1(36.75,146.25) 36.75,144.75 v1(38.25,143.25)
DRN_3: C147.2 C154.1 R226.1 U15.24 | length 8.1
  Top Shielding/Sig w0.25: R226.1@169.3,132.25 169.325,132.25 170.25,131.325 170.25,130.5 170.546,130.204 171.046,130.204 C154.1@171.25,130 ; C147.2@169.5,127.7 169.55,127.75 171,127.75 ; U15.24@171.25,126.9 171.25,127.5 171,127.75 ; C154.1@171.25,129.95 171,129.7 171,127.75
DRN_Q1_7: Q1.5-6-7-8 R21.2 R23.2 | length 43.4
  Top Shielding/Sig w0.25: R23.2@56.55,115.25 v1(57.5,115.25)
  Sig 4 w0.25: v2(54.75,84.5) 58,87.75 58,94.5 59.5,96 62.5,96 64.5,98 64.5,112.25 60.75,116 58.25,116 v1(57.5,115.25)
  other v1: 34.5,86.5 36.5,86.5 38.5,86.5 40.5,86.5
  other v2: 54.75,83
DRN_Q2_7: Q2.5-6-7-8 R26.2 R29.2 RNTC_1.2 | length 30
  Top Shielding/Sig w0.25: R26.2@53.85,91.25 56.75,91.25 58,92.5 58,94.75 59.7,96.45 62.075,96.45 64.25,98.625 64.25,106 63.75,106.5 63.071,106.5 62.925,106.354 62.925,106.35 62.575,106 R29.2@62.55,106 62.55,105.175 61.375,104 RNTC_1.2@58.15,104
  other v1: 44.5,86.5 46.5,86.5 48.5,86.5 50.5,86.5 53.25,87.75
  other v6: 53.75,86.75
DRN_Q3_11: C98.2 C99.2 Q3.5 Q5.5 R111.1 R112.2 R118.2 U9.22 U9.24 | length 36.3
  Top Shielding/Sig w0.25: C99.2@209.2,78.5 209.45,78.25 210.55,78.25 C98.2@210.75,78.45 ; U9.22@210.25,81.85 210.25,81.175 209.75,80.675 209.75,79.475 210.75,78.475 211.75,79.475 211.75,80.75 211.25,81.25 U9.24@211.25,81.85 211.944,81.85 212.5,81.294 v1(212.5,81.25) ; R111.1@212.6,102.5 211,102.5 210.75,102.25 210.75,96.896 210.896,96.75 211.75,96.75 212.75,95.75 R112.2@212.75,94.25 ; v1(212.75,91.5) 212.75,92.45 R118.2@212.8,92.5 R112.2@212.8,94.25
  Sig 4 w0.25: v1(212.5,81.25) 211.75,82 211.75,90.5 v1(212.75,91.5)
  other v1: 212.5,97.5
  other v2: 214.25,97 214.25,98.5 214.25,100 212.5,100.25 214,101.25 217.75,101.25 214,102.5 214,103.75 217.75,103.75 212.5,104.75 214.25,105.25 214.25,106.5 214.25,108
DRN_Q13_2: Q7.5-6-7-8 R153.2 R155.2 | length 53.8
  Top Shielding/Sig w0.25: R155.2@40.75,152.05 v1(40.75,153)
  Sig 1 w0.25: v1(40.75,153) 40.75,153.073 42.677,155 52.5,155 54.25,153.25 v6(72.5,153.25)
  Sig 4 w0.25: v6(72.5,153.25) 74.25,155 v6(74.25,172)
  other v2: 79.25,174.25 79.329,176.196 79.329,178.196 81.5,179.5 83.5,179.5 79.329,180.446 81.475,181.508 83.5,181.5 81.5,183.25 83.5,183.25 74.5,184 81.475,184.758 83.5,184.75 72.25,185.25 76.75,185.25 83.579,186.196 81.5,186.25
DRN_Q18_8: Q14.5 Q14.6 Q14.7 Q14.8 Q14.9 R192.2
  other v5: 198.476,63.976 199.492,63.976 200.508,63.976 198.476,64.992 199.492,64.992 200.508,64.992 198.476,66.008 199.492,66.008 200.508,66.008 198.476,67.024 199.492,67.024 200.508,67.024
DRN_Q19_8: Q15.5 Q15.6 Q15.7 Q15.8 Q15.9 R195.2 R197.2 | length 32.1
  Top Shielding/Sig w0.25: R197.2@185.925,63.125 185.95,63.125 186.5,62.575 186.5,56 188.125,54.375 192,54.375 192.75,55.125 192.75,57.125 193.125,57.5 R195.2@194.71,57.5 ; R195.2@195.25,56.375 195.3,56.375 196.08,55.595 Q15.8@197.219,55.595 197.293,55.669 197.649,55.669 197.979,56 Q15.9@198.476,56 ; R195.2@195.25,56.875 195.26,56.865 Q15.7@197.219,56.865 ; R195.2@195.25,58.125 195.26,58.135 Q15.6@197.219,58.135 198.365,58.135 Q15.9@198.5,58 ; R195.2@195.375,59 195.675,59 196.08,59.405 Q15.5@197.219,59.405 197.574,59.405 197.649,59.331 198.044,59.331 Q15.9@198.375,59 ; Q15.9@198.5,55.952 v5(198.476,55.976) Q15.9@198.476,56 ; Q15.9@198.5,57 198.476,56.976 Q15.9@198.476,56
  other v5: 199.492,55.976 200.508,55.976 198.476,56.992 199.492,56.992 200.508,56.992 198.476,58.008 199.492,58.008 200.508,58.008 198.476,59.024 199.492,59.024 200.508,59.024
DRN_Q21_3: Q17.5-6-7-8 R216.2 R218.2 | length 42
  Top Shielding/Sig w0.25: R218.2@161.75,132.3 161.75,133.411 162,133.661 v1(162,133.75)
  Sig 4 w0.25: v1(162,133.75) 162.75,134.5 162.75,164 v1@169.75,171
  other v1: 174.3,170.369 169.719,171.103 172.05,171.369 170.75,173.25 170.75,175.25 170.75,177.25 170.75,179.25 164.75,180 167,180 164.75,182 167,182 164.75,184 167,184 164.75,186 167,186
DRN_U16_2: Q10.5-6-7-8 Q12.5-6-7-8 R162.2 R163.2 R165.2 R298.1 RNTC_2.2 | length 69.1
  Top Shielding/Sig w0.25: R165.2@45,152.05 v1@45,152.875 ; v1(48,153.25) 49.143,154.393 50.753,154.393 50.896,154.25 v1(51,154.25) 51,154.146 50.75,153.896 50.75,152 52.7,152 R298.1@52.75,151.95 ; v2(49.25,188.2) 51.354,188.2 51.5,188.054 R162.2@51.5,185.15 ; v1(50.75,144) 51.25,144 51.5,144.25 51.5,145.079 51.646,145.225 52.475,145.225 RNTC_2.2@52.5,145.25
  Sig 1 w0.25: v1(45,153) 45.067,152.932 45.067,152.308 45.75,151.625 47.75,151.625 48.074,151.949 48.074,153.176 v1(48,153.25)
  Sig 4 w0.25: v1(48,153.25) 48,153.161 48.25,152.911 48.25,146.5 49.75,145 49.75,144.25 50.074,143.926 50.676,143.926 v1(50.75,144) ; v2(49.25,188.2) 48.646,188.2 48.5,188.054 48.5,175.25 51.5,172.25 51.5,154.75 v1(51,154.25)
  other v1: 49.25,181.75 55.75,181.75 37.78,181.827 65.988,181.833 49.25,183 51.25,183 53.25,183 37.78,183.077 65.988,183.083 55.75,183.5 37.78,184.327 65.988,184.333 49.25,185.25 53.75,185.25 55.75,185.25 37.78,185.577 65.988,185.583
DRV8245_OUT1: C3.2 J8.2 R2.2 U1.8 U1.9 | length 6.8
  Top Shielding/Sig w0.25: v1(175.25,12.25) 176.45,12.25 R2.2@176.5,12.3
  PWR w0.25: J8.2@169.76,12.35 169.86,12.25 v1(175.25,12.25)
  other v2: 168.75,21.25 168.5,28
  other v5: 166,27.75 166,28.55
DRV8245_OUT2: C4.2 J8.1 R1.2 U1.5 U1.6 | length 6.8
  Top Shielding/Sig w0.25: R1.2@153.5,12.3 153.55,12.25 v1(154.75,12.25)
  PWR w0.25: v1(154.75,12.25) 160.14,12.25 J8.1@160.24,12.35
  other v2: 161.25,21.25 161.75,28
  other v5: 164,27.75 164,28.55
DRV8263_OUT1: C21.2 C22.1 J9.2 R15.2 U2.7 | length 7.9
  Top Shielding/Sig w0.25: v1(81.25,12.25) 82.3,12.25 R15.2@82.5,12.05
  Sig 1 w0.25: J9.2@74.76,12.35 74.81,12.3 81.2,12.3 v1(81.25,12.25)
  other v2: 72.75,18.5 72.75,19.5 73.5,21.25
  other v4: 70.5,28.1 71.75,28.1
DRV8263_OUT2: C22.2 C24.2 J9.1 R16.2 U2.5 | length 7.9
  Top Shielding/Sig w0.25: R16.2@57.5,12.05 57.7,12.25 v1(58.75,12.25)
  Sig 1 w0.25: v1(58.75,12.25) 65.14,12.25 J9.1@65.24,12.35
  other v2: 67.25,18.5 67.25,19.5 66.5,21.25
  other v4: 68.25,28.1 69.5,28.1
DRV8363_EBRAKE_1: U16.29 U17.19 | length 85.1
  Top Shielding/Sig w0.25: U16.29@60.562,63.4 60.562,64.938 60.25,65.25 60.25,68.25 v1(61.25,69.25) ; v1(116.5,80.75) 116.5,81.5 117.687,82.687 121.437,82.687 123.25,84.5 123.25,85.455 122.705,86 U17.19@122,86
  Sig 1 w0.25: v1(61.25,69.25) 63.25,71.25 114.75,71.25 116,70 v1(116.642,70)
  Sig 4 w0.25: v1(116.5,80.75) 116.5,80.646 116.642,80.503 v1(116.642,70)
DRV8363_INHA_1: J14.36 U16.11 | length 107.9
  Top Shielding/Sig w0.2: U16.11@62.062,56.6 U16.11@62.062,56.6 62.063,56.187 63,55.25 63,54.5 v1(63.875,53.625)
  Sig 1 w0.25: v1(63.875,53.625) 65.474,52.026 65.474,51.526 66.25,50.75 v1(112.142,50.75) ; v1(122,81) 125.591,81 129.234,84.643 130.026,84.643 132.379,86.995 J14.36@138.43,86.995 138.495,86.995 J14.36@138.5,87
  Sig 4 w0.25: v1(112.142,50.75) 112.092,50.8 112.092,51.475 112,51.568 112,59.5 118.75,66.25 118.75,79.5 120.25,81 v1(122,81)
DRV8363_INHB_1: J14.34 U16.13 | length 113.2
  Top Shielding/Sig w0.2: U16.13@63.212,57.25 63.315,57.25 63.335,57.23 63.335,57.013 v1(63.419,56.93)
  Sig 1 w0.25: v1(63.419,56.93) 63.419,56.831 64.625,55.625 64.625,54.125 67.5,51.25 86.89,51.25 87.015,51.375 v2(106.5,51.375) ; v2(107.25,47.5) 122.5,47.5 v1(123.75,48.75) ; v1(124.5,78) 125.215,78.715 134.465,78.715 137.484,81.734 138.234,81.734 J14.34@138.415,81.915
  Sig 4 w0.25: v2(106.5,51.375) 106.5,48.25 v2(107.25,47.5) ; v1(123.75,48.75) 123.75,77.295 124.455,78 v1(124.5,78)
DRV8363_INHC_1: J14.32 U16.15 | length 96.7
  Top Shielding/Sig w0.2: U16.15@63.212,58.25 64.5,58.25 65,57.75 65,56.929 65.631,56.298 v1(65.631,54.5)
  Sig 1 w0.25: v1(65.631,54.5) 69.25,54.5 70.25,53.5 113.179,53.5 113.429,53.75 v2(113.5,53.75) ; v1(121.25,75.5) 121.354,75.5 121.604,75.75 136.25,75.75 137.25,76.75 138.25,76.75 J14.32@138.5,77
  Sig 4 w0.25: v2(113.5,53.75) 113.5,58.5 121.25,66.25 v1(121.25,75.5)
DRV8363_INLA_1: J14.37 U16.12 | length 126.2
  Top Shielding/Sig w0.2: U16.12@62.562,56.6 62.875,56.6 63.163,56.312 63.674,56.312 63.962,56.6 64.763,56.6 64.932,56.431 64.932,56.182 v1(63.75,55)
  Sig 1 w0.25: v1(63.75,55) 64.129,54.621 64.129,54.414 63.982,54.268 63.609,54.268 63.232,53.891 63.232,53.131 66.114,50.25 100.5,50.25 104.5,46.25 v1(126.25,46.25) ; v1(128,86.25) 129.858,88.108 130.517,88.108 132.301,89.892 136.352,89.892 136.71,89.535 138.215,89.535 J14.37@138.25,89.5
  Sig 4 w0.25: v1(126.25,46.25) 128.548,48.548 128.548,55.65 128.215,55.984 128.215,78.285 128,78.5 v1(128,86.25)
DRV8363_INLB_1: J14.33 U16.14 | length 96
  Top Shielding/Sig w0.2: U16.14@63.212,57.75 63.75,57.75 v1(64.125,57.375)
  Sig 1 w0.25: v1(64.125,57.375) 65.75,55.75 69.25,55.75 70,55 110,55 115,60 v2(122.5,60) ; v1(122.75,76.5) 134,76.5 136.75,79.25 J14.33@138.5,79.25
  Sig 4 w0.25: v2(122.5,60) 122.5,76.146 122.75,76.396 v1(122.75,76.5)
DRV8363_INLC_1: J14.31 U16.16 | length 100.1
  Top Shielding/Sig w0.2: U16.16@63.212,58.75 64.875,58.75 65.5,58.125 65.5,57 67,55.5 v1(67,53.5)
  Sig 1 w0.25: v1(67,53.5) 68,52.5 v1(96.75,52.5) ; v2(96.75,72) 134.5,72 136.75,74.25 J14.31@138.5,74.25
  Sig 4 w0.25: v1(96.75,52.5) v2(96.75,72)
DRV8363_OUTA: C166.2 C169.1 C173.1 J5.1 Q23.1 Q23.2 Q23.3 Q24.5 Q24.6 Q24.7 Q24.8 Q24.9@23.75,75.255 R253.2 R261.2 U16.37 | length 50.3
  Top Shielding/Sig w0.2: C173.1@52.125,65.995 52.179,65.995 52.474,65.7 52.474,65.251 53.35,64.375 54.125,64.375 v1(55.25,63.25) 55.75,62.75 U16.37@56.412,62.75
  Top Shielding/Sig w0.25: Q24.9@23.75,75.255 Q24.9@25.695,77.2 ; C166.2@30,77.2 C166.2@30.1,77.3 ; R253.2@31.75,73.8 R253.2@31.95,74
  Top Shielding/Sig w0.5: Q24.9@25.695,77.2 C166.2@30,77.2 v1(30,75) C169.1@30,73.8 R253.2@31.75,73.8 ; C166.2@30.1,77.3 R261.2@31.75,77.3
  Sig 1 w0.5: v1(30,75) 32.5,75 40,67.5 51,67.5 v1(55.25,63.25)
  other v2: 20.75,73.5 20.75,75.25 20.75,77.25 23.35,77.925 24.65,77.925 25.825,77.925
DRV8363_OUTB: C176.2 C177.1 C179.1 J5.2 Q25.1 Q25.2 Q25.3 Q26.5 Q26.6 Q26.7 Q26.8 Q26.9@23.75,57.755 R254.2 R266.2 U16.44 | length 45.5
  Top Shielding/Sig w0.2: C179.1@53.255,58.5 v1(54.25,58.5) 55,59.25 U16.44@56.412,59.25
  Top Shielding/Sig w0.25: Q26.9@23.75,57.755 Q26.9@25.695,59.7 ; C176.2@30,59.7 C176.2@30.1,59.8 ; R254.2@31.75,56.3 R254.2@31.95,56.5
  Top Shielding/Sig w0.5: Q26.9@25.695,59.7 C176.2@30,59.7 v1(30,57.5) C177.1@30,56.3 R254.2@31.75,56.3 ; C176.2@30.1,59.8 R266.2@31.75,59.8
  Sig 1 w0.5: v1(30,57.5) 40.5,57.5 44.25,53.75 48.25,53.75 53,58.5 v1(54.25,58.5)
  other v2: 20.75,56 20.75,57.75 20.75,59.75 23.35,60.375 25.8,60.375 24.65,60.4
DRV8363_OUTC: C181.1 C183.2 C184.1 J5.3 Q27.1 Q27.2 Q27.3 Q28.5 Q28.6 Q28.7 Q28.8 Q28.9@23.75,40.255 R255.2 R273.2 U16.47 | length 48.6
  Top Shielding/Sig w0.2: C181.1@53.255,56 v1(54.25,56) 55.98,57.73 56.392,57.73 U16.47@56.412,57.75
  Top Shielding/Sig w0.25: Q28.9@23.75,40.255 Q28.5@25.695,42.2 ; C183.2@30,42.2 C183.2@30.1,42.3 ; R255.2@31.75,38.8 R255.2@31.95,39
  Top Shielding/Sig w0.5: Q28.5@25.695,42.2 C183.2@30,42.2 C184.1@30,38.8 R255.2@31.75,38.8 ; C183.2@30.1,42.3 R273.2@31.75,42.3
  Sig 1 w0.5: v1(30,41) 31.5,42.5 36.5,42.5 45.25,51.25 48.5,51.25 53.25,56 v1(54.25,56)
  other v2: 20.5,38.5 20.5,40 20.5,41.5 23.375,42.875 24.625,42.875 25.8,42.875 20.5,43
DRV8363_SOA_1: C186.1 J13.23 R278.1 | length 7.4
  Top Shielding/Sig w0.25: R278.1@91,90.55 C186.1@92.75,90.55 92.95,90.75 96.465,90.75 J13.23@97.79,92.075
DRV8363_SOB_1: C187.1 J13.28 R279.1 | length 7.4
  Top Shielding/Sig w0.25: R279.1@91,77.925 C187.1@92.75,77.925 92.95,78.125 96.54,78.125 J13.28@97.79,79.375
DRV8363_SOC_1: C188.1 J13.26 R280.1 | length 6.5
  Top Shielding/Sig w0.25: J13.26@97.79,84.455 98.545,83.7 C188.1@102,83.7 102.05,83.75 R280.1@103.95,83.75
DRVOFF_DRV82xx_1: U1.10 U2.8 U17.24 | length 168.9
  Top Shielding/Sig w0.25: U2.8@71.625,30.375 72.375,30.375 73,29.75 v1(75.5,29.75) ; U17.24@121.65,88.5 v1(124.25,88.5) ; U1.10@166.625,30.125 168.125,30.125 169.183,31.183 169.433,31.183 v2(169.5,31.25)
  Sig 1 w0.25: v1(84.25,38.25) 112.071,38.25 112.483,38.662 v1(112.587,38.662) ; v1@112.607,38.643 112.642,38.607 144.175,38.607 144.482,38.3 161.45,38.3 163,36.75 v1(169,36.75)
  Sig 4 w0.25: v1(75.5,29.75) 83.926,38.176 84.176,38.176 v1(84.25,38.25) ; v1@112.552,38.75 112.587,38.785 112.587,49.109 112.785,49.306 112.785,59.649 120.125,66.989 120.125,75.284 124.643,79.801 124.643,86.744 124.5,86.886 124.5,88.161 124.25,88.411 v1(124.25,88.5) ; v1(169,36.75) 169.074,36.676 169.324,36.676 169.643,36.357 169.643,33.922 169.5,33.78 v2(169.5,31.25)
DRVOFF_DRV8363_1: U16.9 U17.17 | length 86.8
  Top Shielding/Sig w0.2: U16.9@61.062,56.6 61.062,55.563 v1(61.5,55.125)
  Top Shielding/Sig w0.25: v1(114.25,80.75) 114.272,80.772 114.272,82.395 115.174,83.298 115.32,83.298 116.223,84.2 121.677,84.2 121.824,84.346 121.824,84.975 121.799,85 U17.17@121.65,85
  Sig 1 w0.25: v1(61.5,55.125) 61.5,56.5 65.25,60.25 69.5,60.25 70.25,61 111.75,61 v1(112.25,61.5)
  Sig 4 w0.25: v1(112.25,61.5) 114.25,63.5 v1(114.25,80.75)
EN1_482H85_1: R129.1 R131.1 U17.12 | length 128
  Top Shielding/Sig w0.25: R129.1@39.5,26.95 39.5,26.975 40.7,28.175 40.925,28.175 R131.1@41.25,28.5 ; R131.1@41.25,28.55 v1(41.25,29.75) ; v1(113.75,86.25) 114.5,87 U17.12@117.25,87
  Sig 1 w0.25: v1(41.25,29.75) 41.25,30.5 49,38.25 65.75,38.25 67,39.5 v1(101.5,39.5) ; v1(107,86.25) 107.035,86.215 113.715,86.215 v1(113.75,86.25)
  Sig 4 w0.25: v1(101.5,39.5) 101.5,45.75 103.5,47.75 103.5,69.75 106.5,72.75 106.5,85.75 v1(107,86.25)
EN1_TPS4HC120_1: R90.2 U17.4 | length 167.7
  Top Shielding/Sig w0.25: v1(114.5,93.25) 114.396,93.25 114.146,93 114.1,93 114.1,91.146 114.246,91 U17.4@117.25,91 ; R90.2@199.55,32.5 v1(200.75,32.5)
  Sig 1 w0.2: 172,33.75 173.25,32.5 177.5,32.5 178.8,33.8 197.95,33.8 199.25,32.5 v1(200.75,32.5)
  Sig 1 w0.25: v1(114.5,93.25) 115.75,94.5 115.75,96.75 116.25,97.25 116.25,99.081 116.396,99.227 147.73,99.227 147.933,99.024 147.933,98.817 v2(148,98.75) ; v1(148.75,32.5) 149.25,32 154.5,32 156.25,33.75 160.25,33.75 161.5,32.5 165.25,32.5 166.5,33.75 172,33.75
  Sig 4 w0.25: v2(148,98.75) 148,78.5 147.8,78.3 147.8,74.95 148.75,74 v1(148.75,32.5)
EN2_482H85_1: R130.1 R132.1 U17.13 | length 124
  Top Shielding/Sig w0.25: v1(46.5,29.75) R132.1@46.5,28.05 46.5,28.025 46.85,27.675 46.875,27.675 47.725,26.825 47.925,26.825 R130.1@48.25,26.5 ; v1(114.75,85.75) 115.5,86.5 U17.13@117,86.5
  Sig 1 w0.25: v1(46.5,29.75) 46.5,32.75 51.25,37.5 65.75,37.5 67.142,38.893 92.985,38.893 93.02,38.857 v1@102.022,38.857 ; v1(107.228,85.218) 110.494,85.218 110.605,85.108 114.107,85.108 v1(114.75,85.75)
  Sig 4 w0.25: v1(102.2,38.9) 102.2,45.7 104,47.5 104,69.5 107,72.5 107,84.401 107.155,84.555 107.155,85.145 v1(107.228,85.218)
EN2_TPS4HC120_1: R91.2 U17.5 | length 166.2
  Top Shielding/Sig w0.25: v1(114,94) 113.9,94 113.65,93.75 113.65,90.646 113.796,90.5 U17.5@117.25,90.5 ; R91.2@199.55,34.25 v1(200.75,34.25)
  Sig 1 w0.25: v1(114,94) 114.614,94 115,94.386 115,97 115.75,97.75 115.75,99.364 116.136,99.75 152.007,99.75 153.307,98.45 174.55,98.45 176.094,96.906 v2(178.182,96.906) ; v2(176.25,43.5) 197.672,43.5 198.065,43.107 v1(199,43.107)
  Sig 4 w0.25: v2(176.25,43.5) 178.5,45.75 178.5,96.5 178.25,96.75 v2@178.25,97 ; v1(199,43.107) 201.396,40.711 201.396,34.896 v1(200.75,34.25)
EN3_TPS4HC120_1: R92.2 U17.6 | length 165.5
  Top Shielding/Sig w0.25: v1(113.736,94.792) 113.736,94.736 113.2,94.2 113.2,90.146 113.346,90 U17.6@117.25,90 ; R92.2@199.55,36 v1(200.75,36)
  Sig 1 w0.25: v1(113.736,94.792) 113.736,94.827 114.393,95.484 114.393,97.029 115,97.636 115,99.25 116,100.25 152.214,100.25 153.564,98.9 175.631,98.9 v2(177,97.531) ; v2(175.25,41.5) 197,41.5 197.638,40.862 v1(198.709,40.862)
  Sig 4 w0.25: v2(175.25,41.5) 175.25,43.396 178,46.146 178,95.75 177,96.75 v2(177,97.531) ; v1@199,40.75 200.75,39 v1(200.75,36)
EN4_TPS4HC120_1: R93.2 U17.7 | length 193
  Top Shielding/Sig w0.25: v1(113.75,95.75) 113.646,95.75 112.75,94.854 112.75,89.646 112.896,89.5 U17.7@117.25,89.5 ; v1(199.5,39) 199.5,37.8 R93.2@199.55,37.75
  Sig 1 w0.25: v1(113.75,95.75) 113.824,95.824 113.824,97.096 114.45,97.723 114.45,99.7 115.75,101 v2(152,101) ; v2@152.5,24.75 155,24.75 156,23.75 194.5,23.75 v1(198.25,27.5)
  Sig 4 w0.25: v2(152,101) 153.343,99.658 153.343,33.934 152.477,33.068 v2(152.477,24.867) ; v1(198.25,27.5) 197,28.75 197,37.25 198.75,39 v1(199.5,39)
EN/IN1_DRV8245_1: J14.40 U1.11 | length 96.5
  Top Shielding/Sig w0.25: U1.11@166.625,30.625 167.875,30.625 168.75,31.5 v1(168.75,32.5)
  Sig 1 w0.25: v1(142.5,59.25) v2(158.75,59.25)
  Sig 4 w0.25: J14.40@138.5,97 138.75,97 140,95.75 142.5,95.75 142.75,95.5 142.75,67.114 142.25,66.614 142.25,59.589 142.5,59.339 v1(142.5,59.25) ; v2(158.75,59.25) 166.25,59.25 168,57.5 168,33.25 v1(168.75,32.5)
EN/IN1_DRV8263_1: J15.78 U2.9 | length 80.8
  Top Shielding/Sig w0.25: U2.9@71.625,30.875 72.875,30.875 73.642,31.642 v1(75,31.642)
  Sig 1 w0.25: v1(75,31.642) 75.104,31.642 75.462,32 76.75,32 77.25,31.5 v1(86.25,31.5) ; v2(87.068,36.052) 87.766,36.75 v1(136.25,36.75) ; v1(135.75,28.75) 136.146,28.354 138.104,28.354 J15.78@138.25,28.5
  Sig 4 w0.25: v1(86.25,31.5) 86.25,35.5 86.875,36.125 v2@87,36.125 ; v1(135.75,28.75) 135.75,31.232 135.658,31.325 135.658,36.158 v1(136.25,36.75)
EN_LM74900_1: J18.44 R123.1 U9.6 | length 239.1
  Top Shielding/Sig w0.25: R123.1@211.5,88.95 211.5,87.75 211.9,87.35 ; U9.6@211.9,85 211.9,87.35 ; v1(213.25,87.25) 212,87.25 211.9,87.35
  Sig 1 w0.25: v2(93,4.25) 93.071,4.25 93.321,4 144.75,4 v2(145.5,4.75) ; v1(145.75,20.25) 178.875,20.25 179.842,21.217 179.842,21.467 v2(180.875,22.5) ; v2(181.5,93.75) 207.25,93.75 210.75,90.25 210.75,89.75 v1(213.25,87.25)
  Sig 4 w0.25: v2(93,4.25) 93,23.785 95,25.785 J18.44@95,26 ; v2(145.5,4.75) 145.5,19.896 145.75,20.146 v1(145.75,20.25) ; v2(180.875,22.5) 180.875,93.125 v2(181.5,93.75)
EN_TPS1214_1: J15.57 R35.1 U3.1 | length 196.7
  Top Shielding/Sig w0.25: U3.1@51.25,111.9 51.25,118.25 v1(52,119) R35.1@52.95,119
  Sig 1 w0.25: v1(52,119) 53,120 141.887,120 142.017,120.131 142.631,120.131 v1(142.704,120.204) ; J15.57@141,26 141.035,26.035 143.035,26.035 v1(144,27)
  Sig 4 w0.25: v1(142.704,120.204) 143.7,119.209 143.7,39.25 144,38.95 v1(144,27)
FB_14: C68.1 R53.1 R55.2 U4.3 | length 15.6
  Top Shielding/Sig w0.25: U4.3@125.5,169.95 125.5,171.675 126,172.175 R55.2@126,172.2 126.05,172.25 v1(127.25,172.25) ; R53.1@135.8,170.75 135.775,170.75 135.4,171.125 C68.1@135.4,172.5 v1(136.25,172.5)
  Sig 1 w0.25: v1(127.25,172.25) 133.5,172.25 133.75,172.5 v1(136.25,172.5)
FB_U5_14: R59.2 U5.9 | length 2.4
  Top Shielding/Sig w0.25: U5.9@135.509,142.922 135.509,141.759 135.5,141.75 135.5,141.575 136.25,140.825 R59.2@136.25,140.8
FLT_I_TPS1211_1: D41.1 J18.43 R208.2 U14.5 | length 125.2
  Top Shielding/Sig w0.25: R208.2@170,66.2 v1(170,65) 172.25,62.75 U14.5@176.55,62.75 ; R208.2@170,66.25 169.25,66.25 169,66.5 169,69.75 169.5,70.25 D41.1@170.15,70.25
  Sig 1 w0.25: J18.43@95.125,28.625 96.2,29.7 103.251,29.7 v1(104.201,30.65) ; v2@105,33 136.411,33 136.661,33.25 v1(136.75,33.25) ; v1(137.468,65) 139.718,67.25 166.25,67.25 168.5,65 v1(170,65)
  Sig 4 w0.25: v1@104.25,30.75 104.5,31 104.5,32.529 v2(105.025,33.054) ; v1(136.75,33.25) 136.75,35.7 137.468,36.418 v1(137.468,65)
FLT_T_TPS1211_1: D42.1 J13.7 R210.2 U14.4 | length 112.7
  Top Shielding/Sig w0.2: v1@172,64.75 173.5,63.25 U14.4@176.55,63.25
  Top Shielding/Sig w0.25: v1(172,64.5) 172,64.75 R210.2@172,65.95 ; R210.2@172,66 172.75,66 173.45,66.7 D42.1@173.45,70.25
  Sig 1 w0.25: v2(92.75,63.25) 121.344,63.25 121.379,63.285 149.812,63.285 149.847,63.25 170.75,63.25 v1(172,64.5) ; J13.7@95.067,81.817 J13.7@95.25,82
  Sig 4 w0.25: v2(92.75,63.25) 92.75,81.25 93.25,81.75 J13.7@95.25,81.75
G_TPS1211_8: R193.1 R194.1 TP19.1 U14.11 | length 10
  Top Shielding/Sig w0.25: R194.1@179.5,58.3 R193.1@181.25,58.3 ; U14.11@180.95,60.25 180.95,58.6 R193.1@181.25,58.3 ; TP19.1@183.75,53.75 183.75,56.75 182.2,58.3 R193.1@181.25,58.3
G_TPS1212_input1_2: R157.1 R158.2 TP13.1 U12.13 | length 19.5
  Top Shielding/Sig w0.25: U12.13@41.9,138.75 42.25,138.75 43.175,137.825 44.425,137.825 44.75,137.5 46.484,137.5 46.45,137.466 R157.1@46.45,135.25 46.5,135.2 v1(46.5,134)
  Sig 1 w0.25: v1(46.5,134) 48.5,134 51.25,131.25 TP13.1@56.25,131.25
G_TPS1212_input2_3: R219.1 R221.2 TP23.1 U15.13 | length 15.9
  Top Shielding/Sig w0.25: U15.13@174.4,123.75 175,123.75 175.75,123 179.7,123 R219.1@179.95,123.25 179.95,121.534 R221.2@180.234,121.25 180.25,121.234 v1(180.25,119.5)
  Sig 1 w0.25: v1(180.25,119.5) 182.75,119.5 TP23.1@185.25,117
G_TPS1214_7: R24.1 R25.2 TP4.1 U3.13 | length 31.5
  Top Shielding/Sig w0.25: v1(45.5,103.5) R24.1@44.3,103.5 44.516,103.716 R25.2@44.516,105.5 44.516,105.665 46.951,108.1 U3.13@48.75,108.1
  Sig 4 w0.25: TP4.1@27.5,115 36.25,106.25 42.75,106.25 v1(45.5,103.5)
GATE-_TPS1214_7: D8.1 R38.2 U3.16 | length 12.9
  Top Shielding/Sig w0.25: U3.16@50.25,108.1 50.25,104.25 51.5,103 51.5,100.625 52.625,99.5 D8.1@53.738,99.5 53.45,99.212 R38.2@53.45,97.375
GATE_HA_10: C165.2 C166.1 Q23.4 R261.1 R264.1 | length 26.8
  Top Shielding/Sig w0.25: Q23.4@27.155,78.955 Q23.4@27.2,79
  Top Shielding/Sig w0.5: Q23.4@27.2,79 v1(29,79) 29.8,79 C166.1@30,78.8 30.1,78.7 R261.1@31.75,78.7 ; v1(43.5,68.75) 43.5,67.7 C165.2@43.3,67.5 45.2,67.5 R264.1@45.25,67.55
  Sig 1 w0.5: v1(29,79) 33.25,79 v1(43.5,68.75)
GATE_HB_10: C175.2 C176.1 Q25.4 R266.1 R271.1 | length 20.8
  Top Shielding/Sig w0.5: Q25.4@27.155,61.455 29.845,61.455 C176.1@30,61.3 30.1,61.2 R266.1@31.75,61.2 v1(31.75,62) ; C175.2@43.3,60 C175.2@43.35,60.05 ; v1(43.5,61.25) 43.5,60.2 C175.2@43.35,60.05 ; R271.1@45.25,60.05 C175.2@43.35,60.05
  Sig 1 w0.5: v1(31.75,62) 32.5,61.25 v1(43.5,61.25)
GATE_HC_10: C182.2 C183.1 Q27.4 R273.1 R275.1 | length 22.3
  Top Shielding/Sig w0.5: Q27.4@27.155,43.955 29.845,43.955 30.1,43.7 R273.1@31.75,43.7 31.8,43.75 v1(33,43.75) ; v1(43.25,51.25) 43.25,52.2 C182.2@43.3,52.25 43.35,52.3 R275.1@45.25,52.3
  Sig 1 w0.5: v1(33,43.75) 35.75,43.75 v1(43.25,51.25)
GATE_LA_10: C169.2 C170.1 Q24.4 R265.1 R268.1 | length 31.3
  Top Shielding/Sig w0.25: Q24.4@25.655,71.455 Q24.4@25.678,71.478 ; R268.1@48,63.45 R268.1@48.2,63.25 R268.1@48.05,63.1
  Top Shielding/Sig w0.5: Q24.4@25.678,71.478 26.978,71.478 v1(27,71.5) 27.55,71.5 27.875,71.825 27.9,71.825 28.25,72.175 C170.1@28.25,72.2 C169.2@30,72.2 ; R268.1@48,63.45 v1(48,64.25) ; R265.1@48.05,61.75 R268.1@48.05,63.1
  Sig 1 w0.5: v1(27,71.5) 33.5,71.5 40.75,64.25 v1(48,64.25)
GATE_LB_10: C177.2 C178.1 Q26.4 R270.1 R272.1 | length 22.2
  Top Shielding/Sig w0.25: Q26.4@25.655,53.955 Q26.4@25.678,53.978 ; v1@26.978,53.978 v1(27,54) v1@27.074,54.074 ; R272.1@41.75,55.45 R272.1@41.7,55.5 R272.1@41.8,55.6
  Top Shielding/Sig w0.5: Q26.4@25.678,53.978 v1@26.978,53.978 ; v1@27.074,54.074 27.624,54.074 27.875,54.325 27.9,54.325 28.25,54.675 C178.1@28.25,54.7 C177.2@30,54.7 ; v1(41.75,54.5) R272.1@41.75,55.45 ; R272.1@41.8,55.6 R270.1@41.8,57
  Sig 1 w0.5: v1(27,54) 27.5,54.5 v1(41.75,54.5)
GATE_LC_10: C184.2 C185.1 Q28.4 R276.1 R277.1 | length 32.6
  Top Shielding/Sig w0.25: v1@26.978,36.478 v1(27,36.5) v1@27.074,36.574 ; R276.1@49.45,46 R276.1@49.55,45.9
  Top Shielding/Sig w0.5: Q28.4@25.655,36.455 25.678,36.478 v1@26.978,36.478 ; v1@27.074,36.574 27.624,36.574 27.875,36.825 27.9,36.825 28.25,37.175 C185.1@28.25,37.2 C184.2@30,37.2 ; v1(48.25,46) R276.1@49.45,46 ; R277.1@49.55,44.5 R276.1@49.55,45.9
  Sig 4 w0.5: v1(27,36.5) 31.5,36.5 41,46 v1(48.25,46)
GATE_TPS1211_8: R202.1 R204.2 R205.1 R206.1 | length 6
  Top Shielding/Sig w0.25: R204.2@196.7,51.25 R206.1@194.55,51.25 R205.1@194.55,53 R202.1@196.7,53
